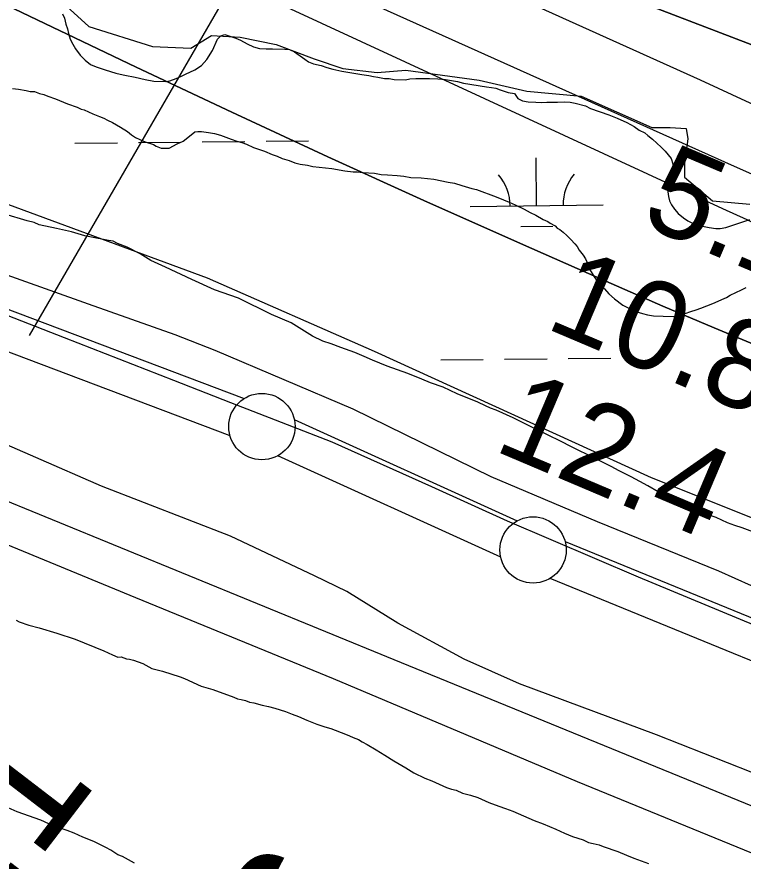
# Model space of a CAD drawing. Extents: x 3651524 to 3689615, y 505651 to 531377.
# Drawn here: x 3661116 to 3661663, y 514096 to 514732 of the extents above; entities that cross this region are included whole.
import ezdxf

# ---------------------------------------------------------------- set-up
doc = ezdxf.new("R2010")
doc.units = 0
for name, color, linetype in [('V-FLOD-BASE', 7, 'Continuous'), ('V-LEVE-TOET', 7, 'Continuous'), ('V-RIVR-EDGE', 7, 'Continuous'), ('V-RIVR-RANG', 7, 'Continuous'), ('V-ROAD-CNTR', 7, 'Continuous'), ('V-SITE-VEGE', 7, 'Continuous'), ('V-SURV-IDEN', 7, 'Continuous'), ('V-SURV-LINE', 7, 'Continuous'), ('V-TOPO-DPTH', 7, 'Continuous'), ('V-TOPO-MINR', 7, 'Continuous'), ('V-TOPO-SHOR', 7, 'Continuous'), ('V-TOPO-WATR', 7, 'Continuous'), ('V-WETL-SWMP', 7, 'Continuous')]:
    doc.layers.add(name, color=color, linetype=linetype)

msp = doc.modelspace()

# ---------------------------------------------------------------- linework, layer by layer
at = {"layer": 'V-FLOD-BASE'}
msp.add_lwpolyline([(3661759.69, 514238.096), (3661685.17, 514268.427), (3661584.668, 514310.075), (3661485.832, 514352.381), (3661429.03, 514378.208), (3661353.899, 514411.847), (3661277.474, 514441.293), (3661234.511, 514458.267), (3661152.286, 514490.228), (3661055.668, 514528.007), (3660957.331, 514563.251), (3660887.897, 514590.852), (3660799.84, 514624.157), (3660719.21, 514654.428), (3660647.671, 514682.326), (3660584.937, 514705.974), (3660516.859, 514731.656), (3660435.263, 514761.018), (3660358.395, 514791.417), (3660278.892, 514820.013), (3660202.246, 514849.934), (3660130.479, 514878.072)], dxfattribs=at)
at = {"layer": 'V-LEVE-TOET'}
for points in [[(3661743.617, 514270.373), (3661645.068, 514314.548), (3661553.831, 514351.703), (3661473.546, 514385.722), (3661369.554, 514436.632), (3661265.6, 514480.727), (3661235.644, 514492.63), (3661170.308, 514515.649), (3661061.504, 514554.484), (3660927.862, 514603.429), (3660822.427, 514644.983), (3660743.393, 514673.565), (3660637.253, 514715.141), (3660517.101, 514759.468), (3660408.176, 514802.3), (3660300.978, 514839.678), (3660215.011, 514872.219), (3660160.898, 514893.505), (3660125.151, 514908.159), (3660097.079, 514920.24), (3660071.802, 514931.537)], [(3661494.892, 514229.857), (3661453.383, 514248.435), (3661403.43, 514275.474), (3661364.893, 514299.366), (3661340.571, 514311.105), (3661277.308, 514340.877), (3661179.983, 514378.675), (3661080.94, 514421.927), (3661010.99, 514447.898), (3660937.5, 514473.266), (3660829.505, 514515.6), (3660754.204, 514543.369), (3660675.184, 514572.42), (3660580.937, 514602.849), (3660488.542, 514632.287), (3660389.969, 514667.537), (3660296.957, 514700.045), (3660199.319, 514735.035), (3660098.623, 514769.878)], [(3662481.799, 513804.737), (3662454.796, 513829.471), (3662420.752, 513854.41), (3662367.5, 513881.075), (3662278.53, 513915.344), (3662188.267, 513953.643), (3662069.524, 514006.152), (3661967.064, 514045.038), (3661881.28, 514075.692), (3661788.61, 514111.95), (3661687.244, 514156.205), (3661598.068, 514191.42), (3661494.892, 514229.857)]]:
    msp.add_lwpolyline(points, dxfattribs=at)
at = {"layer": 'V-RIVR-EDGE'}
for points in [[(3661142.37, 514750.733), (3661170.522, 514724.85), (3661218.51, 514709.723), (3661247.323, 514708.451), (3661262.955, 514718.018), (3661284.564, 514716.764), (3661311.565, 514711.294), (3661340.354, 514700.417)], [(3661340.354, 514700.417), (3661361.948, 514693.159), (3661387.754, 514690.094), (3661409.37, 514691.842), (3661464.582, 514684.501), (3661500.581, 514676.007), (3661541.394, 514672.305), (3661594.764, 514648.76), (3661608.572, 514648.726), (3661620.577, 514648.096), (3661621.758, 514640.289), (3661619.311, 514621.685), (3661619.286, 514611.479), (3661640.252, 514593.417), (3661668.462, 514590.946)]]:
    msp.add_lwpolyline(points, dxfattribs=at)
at = {"layer": 'V-RIVR-RANG'}
msp.add_line((3661125.825, 514492.095), (3661727.025, 515530.632), dxfattribs=at)
at = {"layer": 'V-ROAD-CNTR'}
msp.add_lwpolyline([(3663041.504, 513480.976), (3662699.377, 513664.219), (3662504.781, 513767.955), (3662348.109, 513851.329), (3662249.477, 513899.259), (3662129.876, 513947.868), (3661936.707, 514028.636), (3661400.54, 514247.843), (3660937.042, 514437.744), (3660767.698, 514503.118), (3660635.456, 514548.107), (3660437.74, 514614.376), (3660166.796, 514700.076), (3660103.375, 514721.409)], dxfattribs=at)
at = {"layer": 'V-SITE-VEGE'}
for points in [[(3661113.077, 514678.146), (3661117.669, 514677.632), (3661123.399, 514676.698), (3661126.444, 514675.844)], [(3661126.444, 514675.844), (3661129.512, 514675.756), (3661133.315, 514674.494), (3661136.746, 514673.628), (3661139.781, 514672.389), (3661145.479, 514670.306), (3661154.584, 514666.589), (3661161.803, 514664.078), (3661164.826, 514662.456), (3661167.118, 514662.006), (3661173.561, 514659.134), (3661178.49, 514657.072), (3661181.908, 514655.823), (3661184.548, 514654.211), (3661188.339, 514652.566), (3661194.377, 514648.937), (3661199.658, 514645.716), (3661202.661, 514643.326), (3661205.673, 514641.321), (3661209.079, 514639.687), (3661212.87, 514638.042), (3661219.336, 514635.937), (3661221.22, 514634.73), (3661225.011, 514633.088), (3661231.161, 514633.293), (3661237.012, 514636.58), (3661241.669, 514638.364), (3661245.208, 514641.333), (3661250.316, 514645.409), (3661252.628, 514645.726), (3661255.315, 514645.648), (3661260.67, 514645.11), (3661265.252, 514644.211), (3661269.821, 514642.927), (3661277.796, 514640.01), (3661281.972, 514638.355), (3661285.785, 514637.479), (3661289.201, 514636.228), (3661294.505, 514633.772), (3661299.062, 514632.107), (3661302.865, 514630.845), (3661308.553, 514628.376), (3661312.354, 514627.116), (3661316.145, 514625.471), (3661321.469, 514623.784), (3661325.645, 514622.127), (3661329.842, 514621.238), (3661335.189, 514620.319), (3661339.385, 514619.43), (3661353.541, 514617.869), (3661363.47, 514616.049), (3661369.595, 514615.489), (3661372.663, 514615.399), (3661376.87, 514614.896), (3661385.68, 514614.259), (3661390.645, 514613.349), (3661395.629, 514613.204), (3661402.906, 514612.61), (3661407.881, 514612.084), (3661413.228, 514611.16), (3661420.898, 514610.941), (3661430.464, 514609.896), (3661441.146, 514607.67), (3661446.111, 514606.761), (3661451.435, 514605.071), (3661459.052, 514602.933), (3661462.48, 514602.067), (3661477.293, 514596.65), (3661482.981, 514594.182), (3661487.155, 514592.527), (3661491.703, 514590.477), (3661498.517, 514587.211), (3661503.053, 514584.778), (3661507.217, 514582.738), (3661512.882, 514579.504), (3661516.287, 514577.87), (3661518.174, 514576.666), (3661521.952, 514574.636), (3661523.441, 514573.057), (3661525.327, 514571.853), (3661527.957, 514569.858), (3661530.574, 514567.478), (3661533.554, 514564.324), (3661536.534, 514561.166), (3661538.398, 514559.192), (3661539.854, 514556.464), (3661542.811, 514552.54), (3661544.65, 514549.802), (3661546.096, 514546.689), (3661547.509, 514542.425), (3661548.978, 514540.08), (3661551.169, 514536.179), (3661553.018, 514533.823), (3661554.882, 514531.847), (3661558.968, 514527.126), (3661562.32, 514523.575), (3661566.429, 514519.619), (3661572.816, 514514.828), (3661577.363, 514512.778), (3661581.514, 514510.355), (3661587.607, 514508.645)], [(3661670.772, 514344.271), (3661662.795, 514347.187), (3661657.087, 514348.887), (3661651.773, 514350.96), (3661643.063, 514355.049), (3661637.738, 514356.737), (3661623.713, 514362.899), (3661610.071, 514369.05), (3661599.477, 514374.346), (3661591.545, 514378.796), (3661585.497, 514382.04), (3661579.077, 514385.679), (3661569.992, 514390.162), (3661563.944, 514393.408), (3661559.025, 514395.854), (3661550.71, 514400.314), (3661540.104, 514405.225), (3661532.532, 514408.9), (3661527.24, 514411.738), (3661515.134, 514417.843), (3661509.83, 514420.301), (3661490.153, 514430.078), (3661477.267, 514435.823), (3661473.095, 514437.479), (3661469.302, 514439.124), (3661463.627, 514441.975), (3661448.068, 514448.178), (3661437.464, 514453.093), (3661427.963, 514456.436), (3661421.52, 514459.307), (3661410.893, 514463.452), (3661395.312, 514468.89), (3661384.31, 514473.428), (3661377.869, 514476.301), (3661371.043, 514479.187), (3661360.404, 514482.945), (3661353.195, 514485.841), (3661346.729, 514487.946), (3661339.16, 514491.618), (3661322.944, 514501.68), (3661308.151, 514507.865), (3661283.172, 514520.098), (3661265.311, 514526.371), (3661248.264, 514534.155), (3661228.191, 514543.562), (3661217.202, 514548.483), (3661209.29, 514553.701), (3661199.452, 514558.592), (3661192.245, 514561.486), (3661188.835, 514563.118), (3661185.394, 514563.601), (3661181.581, 514564.48), (3661176.233, 514565.402), (3661167.458, 514567.189), (3661157.564, 514570.161), (3661152.982, 514571.06), (3661146.124, 514572.791), (3661133.152, 514575.47), (3661129.361, 514577.114), (3661124.024, 514578.419), (3661107.281, 514583.508)], [(3661587.607, 514508.645), (3661591.42, 514507.769), (3661596, 514506.868), (3661603.286, 514506.659), (3661610.958, 514506.438), (3661615.583, 514507.072), (3661624.119, 514510.282), (3661627.987, 514511.32), (3661631.483, 514512.756), (3661636.14, 514514.539), (3661639.241, 514515.602), (3661642.356, 514517.048), (3661647.406, 514519.207), (3661650.902, 514520.64), (3661653.643, 514522.482), (3661662.201, 514526.457), (3661665.707, 514528.275)], [(3661115.75, 514277.731), (3661118.021, 514276.517), (3661125.238, 514274.006), (3661133.238, 514271.856), (3661146.562, 514268.018), (3661160.245, 514263.401), (3661181.874, 514254.718), (3661188.308, 514251.462), (3661192.48, 514249.807), (3661194.792, 514250.122), (3661198.966, 514248.467), (3661201.268, 514248.402), (3661204.313, 514247.546), (3661211.152, 514245.045), (3661217.955, 514241.398), (3661225.955, 514239.245), (3661239.267, 514235.024), (3661242.685, 514233.773), (3661255.188, 514228.041), (3661263.941, 514225.485), (3661279.895, 514219.652), (3661282.545, 514218.423), (3661285.22, 514217.962), (3661288.648, 514217.096), (3661291.683, 514215.857), (3661294.741, 514215.386), (3661301.217, 514213.662), (3661305.798, 514212.765), (3661310.752, 514211.47), (3661318.737, 514208.939), (3661323.669, 514206.877), (3661328.609, 514205.199), (3661334.669, 514202.336), (3661342.261, 514199.432), (3661348.341, 514197.337), (3661352.91, 514196.055), (3661363.922, 514191.9), (3661366.957, 514190.661), (3661369.61, 514189.432), (3661373.783, 514187.777), (3661376.423, 514186.165), (3661380.204, 514184.138), (3661386.997, 514180.103), (3661393.407, 514176.081), (3661400.188, 514171.663), (3661409.249, 514166.412), (3661415.286, 514162.783), (3661423.613, 514158.706), (3661428.928, 514156.633), (3661439.917, 514151.712), (3661443.719, 514150.45), (3661447.151, 514149.584), (3661452.078, 514147.519), (3661458.171, 514145.811), (3661463.496, 514144.124), (3661471.833, 514140.427), (3661479.427, 514137.523), (3661484.369, 514135.846), (3661490.067, 514133.761), (3661505.984, 514126.777), (3661512.822, 514124.279), (3661522.3, 514120.166), (3661528.743, 514117.293), (3661534.814, 514114.817), (3661542.801, 514112.284), (3661546.964, 514110.244), (3661550.395, 514109.377), (3661554.974, 514108.478), (3661558.009, 514107.239)], [(3661204.903, 514094.763), (3661195.833, 514099.627), (3661192.415, 514100.878), (3661187.145, 514104.485), (3661183.364, 514106.512), (3661174.282, 514110.997), (3661165.932, 514114.307), (3661159.489, 514117.18), (3661154.174, 514119.253), (3661148.85, 514120.943), (3661140.502, 514124.252), (3661134.442, 514127.113), (3661116.583, 514133.384), (3661109.757, 514136.27)], [(3661558.009, 514107.239), (3661569.032, 514103.467), (3661575.475, 514100.596), (3661581.172, 514098.513), (3661592.184, 514094.355)]]:
    msp.add_lwpolyline(points, dxfattribs=at)
at = {"layer": 'V-SURV-LINE'}
for points in [[(3660148.471, 514875.327), (3661287.512, 514444.608)], [(3661276.893, 514416.55), (3660137.852, 514847.269)], [(3661325.275, 514428.898), (3661493.203, 514352.498)], [(3661480.786, 514325.189), (3661312.857, 514401.588)], [(3661529.357, 514336.889), (3662394.846, 513982.965)], [(3662383.482, 513955.2), (3661517.993, 514309.124)]]:
    msp.add_lwpolyline(points, dxfattribs=at)
for centre in [(3661300.886, 514423.514), (3661505.175, 514330.572)]:
    msp.add_circle(centre, 25, dxfattribs=at)
at = {"layer": 'V-TOPO-DPTH'}
for points in [[(3661698.922, 514700.068), (3661602.485, 514736.825), (3661542.422, 514760.284), (3661482.627, 514784.395), (3661423.236, 514809.484), (3661364.114, 514835.225), (3660637.13, 515158.864), (3660617.422, 515168.33), (3660598.129, 515178.529), (3660579.458, 515189.825), (3660561.202, 515201.855), (3659835.435, 515710.798)], [(3661698.922, 514700.068), (3661602.485, 514736.825), (3661542.422, 514760.284), (3661482.627, 514784.395), (3661423.236, 514809.484), (3661364.114, 514835.225), (3660637.13, 515158.864), (3660617.422, 515168.33), (3660598.129, 515178.529), (3660579.458, 515189.825), (3660561.202, 515201.855), (3659835.435, 515710.798)], [(3659882.5, 515644.592), (3660240.174, 515355.97), (3660292.73, 515314.335), (3660345.77, 515273.338), (3660399.537, 515233.3), (3660453.789, 515193.901), (3660552.13, 515123.822), (3660557.669, 515120.104), (3660563.332, 515116.6), (3660569.182, 515113.417), (3660575.157, 515110.448), (3660760.23, 515024.846), (3660858.91, 514979.404), (3660957.691, 514934.182), (3661056.623, 514889.291), (3661155.655, 514844.621), (3661656.606, 514619.666), (3661671.902, 514612.741)], [(3659882.5, 515644.592), (3660240.174, 515355.97), (3660292.73, 515314.335), (3660345.77, 515273.338), (3660399.537, 515233.3), (3660453.789, 515193.901), (3660552.13, 515123.822), (3660557.669, 515120.104), (3660563.332, 515116.6), (3660569.182, 515113.417), (3660575.157, 515110.448), (3660760.23, 515024.846), (3660858.91, 514979.404), (3660957.691, 514934.182), (3661056.623, 514889.291), (3661155.655, 514844.621), (3661656.606, 514619.666), (3661671.902, 514612.741)], [(3662644.311, 514103.201), (3662090.264, 514319.377), (3662015.342, 514348.705), (3661940.463, 514378.144), (3661865.65, 514407.747), (3661790.88, 514437.461), (3661719.927, 514465.749), (3661680.755, 514481.612), (3661641.701, 514497.756), (3661602.823, 514514.32), (3661564.064, 514531.166), (3661495.695, 514561.32), (3661422.991, 514593.784), (3661350.49, 514626.689), (3661278.293, 514660.256), (3661206.299, 514694.263), (3660527.5, 515018.706), (3660520.041, 515022.492), (3660512.716, 515026.508), (3660505.59, 515030.868), (3660498.598, 515035.458), (3660317.459, 515160.641), (3660220.777, 515229.04), (3660125.134, 515298.829)]]:
    msp.add_lwpolyline(points, dxfattribs=at)
at = {"layer": 'V-TOPO-MINR'}
for points in [[(3659719.87, 515787.056), (3660555.664, 515200.604), (3660575.638, 515187.312), (3660596.009, 515174.699), (3660616.978, 515163.104), (3660638.344, 515152.189), (3661118.8, 514921.505), (3661216.134, 514875.193), (3661313.682, 514829.34), (3661411.55, 514784.176), (3661509.633, 514739.471), (3661631.171, 514684.591), (3661668.457, 514667.291), (3661705.493, 514649.484), (3661742.155, 514630.919), (3661778.567, 514611.847), (3661930.817, 514530.093), (3662043.718, 514470.876), (3662157.353, 514413.14), (3662272.09, 514357.626), (3662387.561, 514303.593), (3662676.518, 514171.792)], [(3659835.435, 515710.798), (3660561.202, 515201.855), (3660579.458, 515189.825), (3660598.129, 515178.529), (3660617.422, 515168.33), (3660637.13, 515158.864), (3661364.114, 514835.225), (3661423.236, 514809.484), (3661482.627, 514784.395), (3661542.422, 514760.284), (3661602.485, 514736.825), (3661698.922, 514700.068)], [(3660085.326, 515424.778), (3660520.018, 515116.583), (3660535.762, 515106.061), (3660551.854, 515096.142), (3660568.469, 515087.125), (3660585.432, 515078.709), (3661651.207, 514586.175), (3661655.077, 514584.394), (3661658.951, 514582.622), (3661662.832, 514580.863), (3661666.716, 514579.113), (3661670.784, 514577.288), (3661672.638, 514576.457), (3661676.345, 514574.798), (3661680.054, 514573.143), (3661681.91, 514572.32), (3661685.628, 514570.684), (3662689.887, 514131.012), (3662705.505, 514124.232), (3662721.149, 514117.517), (3662736.835, 514110.897), (3662752.548, 514104.342), (3662768.295, 514097.869), (3662784.059, 514091.439)], [(3660125.134, 515298.829), (3660220.777, 515229.04), (3660317.459, 515160.641), (3660498.598, 515035.458), (3660505.59, 515030.868), (3660512.716, 515026.508), (3660520.041, 515022.492), (3660527.5, 515018.706), (3661206.299, 514694.263), (3661278.293, 514660.256), (3661350.49, 514626.689), (3661422.991, 514593.784), (3661495.695, 514561.32), (3661564.064, 514531.166), (3661602.823, 514514.32), (3661641.701, 514497.756), (3661680.755, 514481.612), (3661719.927, 514465.749), (3661790.88, 514437.461), (3661865.65, 514407.747), (3661940.463, 514378.144), (3662015.342, 514348.705), (3662090.264, 514319.377), (3662644.311, 514103.201)]]:
    msp.add_lwpolyline(points, dxfattribs=at)
at = {"layer": 'V-TOPO-SHOR'}
msp.add_lwpolyline([(3660464.428, 514570.563), (3660645.715, 514509.864), (3660837.363, 514443.044), (3661047.871, 514359.909), (3661205.737, 514294.826), (3661354.563, 514233.816), (3661538.525, 514156.279), (3661675.284, 514100.196), (3661799.329, 514053.127), (3661813.378, 514046.365), (3661822.912, 514041.765), (3661829.65, 514037.247), (3661833.621, 514033.827), (3661834.114, 514033.302), (3661839.21, 514024.762)], dxfattribs=at)
at = {"layer": 'V-TOPO-WATR'}
msp.add_lwpolyline([(3659882.5, 515644.592), (3660240.174, 515355.97), (3660292.73, 515314.335), (3660345.77, 515273.338), (3660399.537, 515233.3), (3660453.789, 515193.901), (3660552.13, 515123.822), (3660557.669, 515120.104), (3660563.332, 515116.6), (3660569.182, 515113.417), (3660575.157, 515110.448), (3660760.23, 515024.846), (3660858.91, 514979.404), (3660957.691, 514934.182), (3661056.623, 514889.291), (3661155.655, 514844.621), (3661656.606, 514619.666), (3661671.902, 514612.741)], dxfattribs=at)
at = {"layer": 'V-WETL-SWMP'}
for p, q in [((3661160.043, 514636.872), (3661192.041, 514637.216)), ((3661208.04, 514637.389), (3661240.038, 514637.733)), ((3661256.037, 514637.905), (3661288.035, 514638.25)), ((3661304.034, 514638.422), (3661336.032, 514638.766)), ((3661507.885, 514589.871), (3661507.497, 514625.869)), ((3661457.887, 514589.333), (3661557.882, 514590.409)), ((3661496.051, 514574.312), (3661520.05, 514574.57)), ((3661435.723, 514473.656), (3661467.721, 514474)), ((3661483.72, 514474.172), (3661515.719, 514474.517)), ((3661531.718, 514474.689), (3661563.716, 514475.033))]:
    msp.add_line(p, q, dxfattribs=at)
for points in [[(3661701.85, 514341.948), (3661594.462, 514384.904), (3661385.823, 514480.019), (3661260.025, 514535.247), (3660943.998, 514651.84), (3660652.516, 514765.364), (3660207.623, 514931.048), (3660066.484, 514989.345)], [(3661150.665, 514734.256), (3661152.256, 514731.084), (3661153.326, 514726.485), (3661154.43, 514723.087), (3661155.288, 514719.456), (3661156.611, 514715.331), (3661158.423, 514711.432), (3661160.488, 514708.006), (3661163.96, 514703.338), (3661167.693, 514699.384)], [(3661167.693, 514699.384), (3661171.687, 514696.143), (3661175.962, 514694.337), (3661182.874, 514692.215), (3661190.972, 514689.577), (3661194.082, 514689.007), (3661197.664, 514688.182), (3661205.557, 514686.753), (3661212.956, 514684.857), (3661219.415, 514683.709), (3661228.303, 514683.453), (3661231.68, 514683.837), (3661236.3, 514685.627), (3661240.439, 514687.431), (3661243.37, 514689.03), (3661250.434, 514692.192), (3661255.335, 514695.417), (3661259.551, 514699.864), (3661263.595, 514706.72), (3661267.448, 514715.265), (3661269.926, 514717.838), (3661273.077, 514718.709), (3661276.653, 514717.644), (3661281.175, 514716.071), (3661284.737, 514714.526), (3661289.706, 514711.738), (3661294.689, 514709.431), (3661299.225, 514708.339), (3661304.023, 514707.96), (3661308.835, 514708.062), (3661318.204, 514707.792), (3661321.8, 514707.448), (3661325.355, 514705.663), (3661333.371, 514700.142), (3661335.958, 514698.144), (3661339.767, 514696.833), (3661345.498, 514695.465), (3661349.781, 514693.9), (3661354.317, 514692.807), (3661361.243, 514691.165), (3661376.075, 514688.574), (3661381.346, 514687.941), (3661384.929, 514687.117), (3661388.285, 514686.78), (3661393.302, 514685.674), (3661396.906, 514685.57), (3661400.495, 514684.986), (3661409.143, 514684.737), (3661412.287, 514685.367), (3661416.865, 514685.716), (3661420.469, 514685.613), (3661427.202, 514685.659), (3661433.448, 514685.479), (3661439.2, 514684.833), (3661448.294, 514683.369), (3661452.831, 514682.276), (3661470.058, 514679.376), (3661473.888, 514678.785), (3661477.244, 514678.448), (3661480.333, 514677.157), (3661486.524, 514675.055), (3661491.314, 514674.436), (3661493.606, 514670.523), (3661497.161, 514668.738), (3661501.471, 514668.133), (3661507.23, 514667.727), (3661511.554, 514667.602), (3661515.645, 514667.725), (3661523.579, 514667.737), (3661528.638, 514668.072), (3661533.202, 514667.94), (3661536.785, 514667.116), (3661544.657, 514664.966), (3661548.453, 514663.173), (3661562.255, 514658.208), (3661568.438, 514655.866), (3661575.796, 514652.528), (3661581.238, 514649.487), (3661585.005, 514646.733), (3661589.274, 514644.687), (3661591.621, 514642.696), (3661595.149, 514639.95), (3661601.709, 514633.99), (3661604.749, 514631.018), (3661609.154, 514625.361), (3661610.485, 514621.476), (3661610.635, 514618.346), (3661608.279, 514611.682), (3661606.693, 514606.678), (3661605.875, 514603.336), (3661606.746, 514600.185), (3661607.13, 514596.808), (3661607.994, 514593.417), (3661609.352, 514590.493), (3661611.665, 514587.301), (3661614.457, 514584.095), (3661618.445, 514580.614), (3661621.746, 514578.355), (3661625.307, 514576.81), (3661630.304, 514574.983), (3661637.95, 514573.32)], [(3661637.95, 514573.32), (3661642.981, 514572.694), (3661646.104, 514572.604), (3661650.456, 514573.441), (3661653.373, 514574.559), (3661663.319, 514577.638), (3661668.419, 514579.415)]]:
    msp.add_lwpolyline(points, dxfattribs=at)
for centre, start, end in [((3661452.64, 514589.751), 359.844864, 41.388523), ((3661563.119, 514590.94), 139.844861, 181.38852)]:
    msp.add_arc(centre, 35.246, start, end, dxfattribs=at)

# ---------------------------------------------------------------- texts
at = {"layer": 'V-RIVR-RANG'}
for s, p in [('5.1', (3661584.632, 514576.543)), ('10.8', (3661513.042, 514498.277)), ('12.4', (3661474.237, 514406.113))]:
    msp.add_text(s, height=67, rotation=337.028326, dxfattribs=at).set_placement(p)
at = {"layer": 'V-SURV-IDEN'}
for s, rotation, p in [('725+65.1', 52.502876, (3660834.998, 513709.034)), ('727+89.6', 51.919656, (3661040.504, 513613.379))]:
    msp.add_text(s, height=100, rotation=rotation, dxfattribs=at).set_placement(p)

doc.saveas('drawing.dxf')
